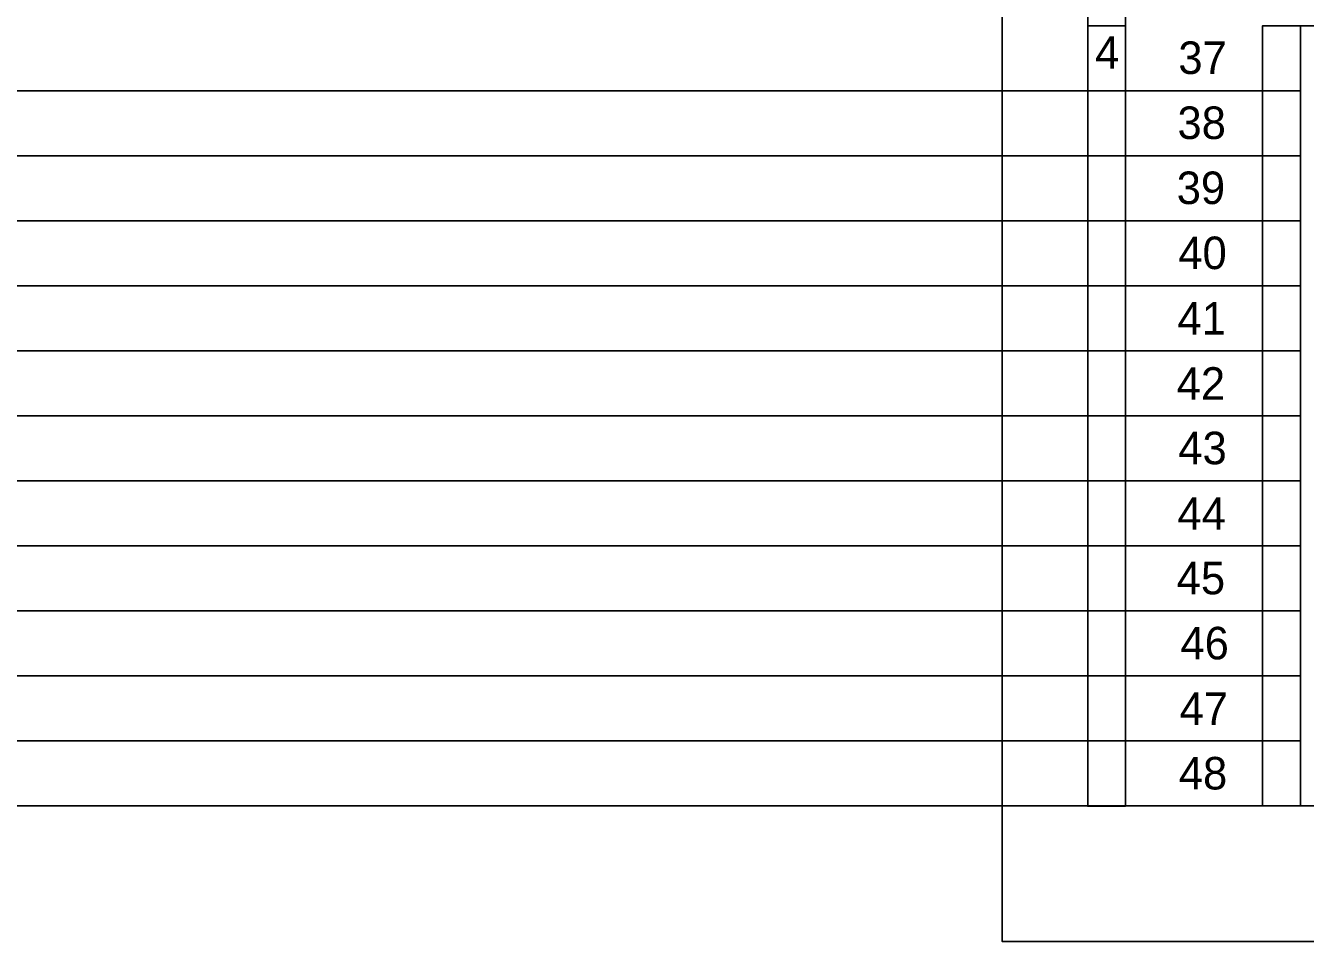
# Model space of a CAD drawing. Extents: x 1901 to 2519, y -3585 to -3154.
# Drawn here: x 2318.6 to 2387.9, y -3379.3 to -3329.7 of the extents above; entities that cross this region are included whole.
import ezdxf

# ---------------------------------------------------------------- set-up
doc = ezdxf.new("R2010")
doc.units = 0
doc.layers.add('rozvláknění', color=7, linetype='Continuous')

msp = doc.modelspace()

# ---------------------------------------------------------------- linework, layer by layer
at = {"layer": 'rozvláknění'}
for p, q in [((2253.932, -3333.246), (2385.56, -3333.245)), ((2253.932, -3336.764), (2385.56, -3336.763)), ((2253.932, -3340.282), (2385.56, -3340.281)), ((2253.932, -3343.8), (2385.56, -3343.799)), ((2253.932, -3347.318), (2385.56, -3347.318)), ((2253.932, -3350.837), (2385.56, -3350.836)), ((2253.932, -3354.355), (2385.56, -3354.354)), ((2253.932, -3357.873), (2385.56, -3357.872)), ((2253.932, -3361.391), (2385.56, -3361.39)), ((2253.932, -3364.909), (2385.56, -3364.909)), ((2253.932, -3368.428), (2385.56, -3368.427)), ((2253.932, -3371.946), (2385.56, -3371.945))]:
    msp.add_line(p, q, dxfattribs=at)
for points in [[(2371.457, -3178.543), (2405.455, -3178.542), (2405.455, -3379.276), (2371.457, -3379.276)], [(2378.138, -3371.959), (2376.097, -3371.959), (2376.097, -3287.487), (2378.138, -3287.487)], [(2378.138, -3371.945), (2376.097, -3371.945), (2376.097, -3329.727), (2378.138, -3329.727)], [(2385.56, -3329.727), (2387.602, -3329.727), (2387.602, -3333.245), (2385.56, -3333.245)], [(2385.56, -3329.727), (2387.602, -3329.727), (2387.602, -3333.245), (2385.56, -3333.245)], [(2387.602, -3329.727), (2390.389, -3329.727), (2390.389, -3371.941), (2387.602, -3371.941)], [(2385.56, -3333.245), (2387.602, -3333.245), (2387.602, -3336.763), (2385.56, -3336.763)], [(2385.56, -3333.245), (2387.602, -3333.245), (2387.602, -3336.763), (2385.56, -3336.763)], [(2385.56, -3336.763), (2387.602, -3336.763), (2387.602, -3340.281), (2385.56, -3340.281)], [(2385.56, -3336.763), (2387.602, -3336.763), (2387.602, -3340.281), (2385.56, -3340.281)], [(2385.56, -3340.281), (2387.602, -3340.281), (2387.602, -3343.799), (2385.56, -3343.799)], [(2385.56, -3340.281), (2387.602, -3340.281), (2387.602, -3343.799), (2385.56, -3343.799)], [(2385.56, -3343.799), (2387.602, -3343.799), (2387.602, -3347.318), (2385.56, -3347.318)], [(2385.56, -3343.799), (2387.602, -3343.799), (2387.602, -3347.318), (2385.56, -3347.318)], [(2385.56, -3347.318), (2387.602, -3347.318), (2387.602, -3350.836), (2385.56, -3350.836)], [(2385.56, -3347.318), (2387.602, -3347.318), (2387.602, -3350.836), (2385.56, -3350.836)], [(2385.56, -3350.836), (2387.602, -3350.836), (2387.602, -3354.354), (2385.56, -3354.354)], [(2385.56, -3350.836), (2387.602, -3350.836), (2387.602, -3354.354), (2385.56, -3354.354)], [(2385.56, -3354.354), (2387.602, -3354.354), (2387.602, -3357.872), (2385.56, -3357.872)], [(2385.56, -3354.354), (2387.602, -3354.354), (2387.602, -3357.872), (2385.56, -3357.872)], [(2385.56, -3357.872), (2387.602, -3357.872), (2387.602, -3361.39), (2385.56, -3361.39)], [(2385.56, -3357.872), (2387.602, -3357.872), (2387.602, -3361.39), (2385.56, -3361.39)], [(2385.56, -3361.39), (2387.602, -3361.39), (2387.602, -3364.909), (2385.56, -3364.909)], [(2385.56, -3361.39), (2387.602, -3361.39), (2387.602, -3364.909), (2385.56, -3364.909)], [(2385.56, -3364.909), (2387.602, -3364.909), (2387.602, -3368.427), (2385.56, -3368.427)], [(2385.56, -3364.909), (2387.602, -3364.909), (2387.602, -3368.427), (2385.56, -3368.427)], [(2385.56, -3368.427), (2387.602, -3368.427), (2387.602, -3371.945), (2385.56, -3371.945)], [(2385.56, -3368.427), (2387.602, -3368.427), (2387.602, -3371.945), (2385.56, -3371.945)]]:
    msp.add_lwpolyline(points, close=True, dxfattribs=at)
for points in [[(2378.138, -3329.727), (2376.097, -3329.727), (2376.097, -3371.945), (2378.138, -3371.945), (2378.138, -3329.727)], [(2378.138, -3329.727), (2376.097, -3329.727), (2376.097, -3371.945), (2378.138, -3371.945), (2378.138, -3329.727)], [(2378.138, -3329.727), (2376.097, -3329.727), (2376.097, -3371.945), (2378.138, -3371.945), (2378.138, -3329.727)], [(2378.138, -3329.727), (2376.097, -3329.727), (2376.097, -3371.945), (2378.138, -3371.945), (2378.138, -3329.727)], [(2378.138, -3329.727), (2376.097, -3329.727), (2376.097, -3371.945), (2378.138, -3371.945), (2378.138, -3329.727)], [(2378.138, -3329.727), (2376.097, -3329.727), (2376.097, -3371.945), (2378.138, -3371.945), (2378.138, -3329.727)], [(2385.56, -3333.245), (2387.602, -3333.245), (2387.602, -3329.727), (2385.56, -3329.727), (2385.56, -3333.245)], [(2385.56, -3333.245), (2387.602, -3333.245), (2387.602, -3329.727), (2385.56, -3329.727), (2385.56, -3333.245)], [(2385.56, -3333.245), (2387.602, -3333.245), (2387.602, -3329.727), (2385.56, -3329.727), (2385.56, -3333.245)], [(2385.56, -3333.245), (2387.602, -3333.245), (2387.602, -3329.727), (2385.56, -3329.727), (2385.56, -3333.245)], [(2385.56, -3333.245), (2387.602, -3333.245), (2387.602, -3329.727), (2385.56, -3329.727), (2385.56, -3333.245)], [(2385.56, -3333.245), (2387.602, -3333.245), (2387.602, -3329.727), (2385.56, -3329.727), (2385.56, -3333.245)], [(2385.56, -3333.245), (2387.602, -3333.245), (2387.602, -3329.727), (2385.56, -3329.727), (2385.56, -3333.245)], [(2385.56, -3333.245), (2387.602, -3333.245), (2387.602, -3329.727), (2385.56, -3329.727), (2385.56, -3333.245)], [(2385.56, -3333.245), (2387.602, -3333.245), (2387.602, -3329.727), (2385.56, -3329.727), (2385.56, -3333.245)], [(2385.56, -3333.245), (2387.602, -3333.245), (2387.602, -3329.727), (2385.56, -3329.727), (2385.56, -3333.245)], [(2385.56, -3333.243), (2385.56, -3368.443)], [(2385.56, -3336.763), (2387.602, -3336.763), (2387.602, -3333.245), (2385.56, -3333.245), (2385.56, -3336.763)], [(2385.56, -3336.763), (2387.602, -3336.763), (2387.602, -3333.245), (2385.56, -3333.245), (2385.56, -3336.763)], [(2385.56, -3336.763), (2387.602, -3336.763), (2387.602, -3333.245), (2385.56, -3333.245), (2385.56, -3336.763)], [(2385.56, -3336.763), (2387.602, -3336.763), (2387.602, -3333.245), (2385.56, -3333.245), (2385.56, -3336.763)], [(2385.56, -3336.763), (2387.602, -3336.763), (2387.602, -3333.245), (2385.56, -3333.245), (2385.56, -3336.763)], [(2385.56, -3336.763), (2387.602, -3336.763), (2387.602, -3333.245), (2385.56, -3333.245), (2385.56, -3336.763)], [(2385.56, -3336.763), (2387.602, -3336.763), (2387.602, -3333.245), (2385.56, -3333.245), (2385.56, -3336.763)], [(2385.56, -3336.763), (2387.602, -3336.763), (2387.602, -3333.245), (2385.56, -3333.245), (2385.56, -3336.763)], [(2385.56, -3336.763), (2387.602, -3336.763), (2387.602, -3333.245), (2385.56, -3333.245), (2385.56, -3336.763)], [(2385.56, -3336.763), (2387.602, -3336.763), (2387.602, -3333.245), (2385.56, -3333.245), (2385.56, -3336.763)], [(2385.56, -3340.281), (2387.602, -3340.281), (2387.602, -3336.763), (2385.56, -3336.763), (2385.56, -3340.281)], [(2385.56, -3340.281), (2387.602, -3340.281), (2387.602, -3336.763), (2385.56, -3336.763), (2385.56, -3340.281)], [(2385.56, -3340.281), (2387.602, -3340.281), (2387.602, -3336.763), (2385.56, -3336.763), (2385.56, -3340.281)], [(2385.56, -3340.281), (2387.602, -3340.281), (2387.602, -3336.763), (2385.56, -3336.763), (2385.56, -3340.281)], [(2385.56, -3340.281), (2387.602, -3340.281), (2387.602, -3336.763), (2385.56, -3336.763), (2385.56, -3340.281)], [(2385.56, -3340.281), (2387.602, -3340.281), (2387.602, -3336.763), (2385.56, -3336.763), (2385.56, -3340.281)], [(2385.56, -3340.281), (2387.602, -3340.281), (2387.602, -3336.763), (2385.56, -3336.763), (2385.56, -3340.281)], [(2385.56, -3340.281), (2387.602, -3340.281), (2387.602, -3336.763), (2385.56, -3336.763), (2385.56, -3340.281)], [(2385.56, -3340.281), (2387.602, -3340.281), (2387.602, -3336.763), (2385.56, -3336.763), (2385.56, -3340.281)], [(2385.56, -3340.281), (2387.602, -3340.281), (2387.602, -3336.763), (2385.56, -3336.763), (2385.56, -3340.281)], [(2385.56, -3343.799), (2387.602, -3343.799), (2387.602, -3340.281), (2385.56, -3340.281), (2385.56, -3343.799)], [(2385.56, -3343.799), (2387.602, -3343.799), (2387.602, -3340.281), (2385.56, -3340.281), (2385.56, -3343.799)], [(2385.56, -3343.799), (2387.602, -3343.799), (2387.602, -3340.281), (2385.56, -3340.281), (2385.56, -3343.799)], [(2385.56, -3343.799), (2387.602, -3343.799), (2387.602, -3340.281), (2385.56, -3340.281), (2385.56, -3343.799)], [(2385.56, -3343.799), (2387.602, -3343.799), (2387.602, -3340.281), (2385.56, -3340.281), (2385.56, -3343.799)], [(2385.56, -3343.799), (2387.602, -3343.799), (2387.602, -3340.281), (2385.56, -3340.281), (2385.56, -3343.799)], [(2385.56, -3343.799), (2387.602, -3343.799), (2387.602, -3340.281), (2385.56, -3340.281), (2385.56, -3343.799)], [(2385.56, -3343.799), (2387.602, -3343.799), (2387.602, -3340.281), (2385.56, -3340.281), (2385.56, -3343.799)], [(2385.56, -3343.799), (2387.602, -3343.799), (2387.602, -3340.281), (2385.56, -3340.281), (2385.56, -3343.799)], [(2385.56, -3343.799), (2387.602, -3343.799), (2387.602, -3340.281), (2385.56, -3340.281), (2385.56, -3343.799)], [(2385.56, -3347.318), (2387.602, -3347.318), (2387.602, -3343.799), (2385.56, -3343.799), (2385.56, -3347.318)], [(2385.56, -3347.318), (2387.602, -3347.318), (2387.602, -3343.799), (2385.56, -3343.799), (2385.56, -3347.318)], [(2385.56, -3347.318), (2387.602, -3347.318), (2387.602, -3343.799), (2385.56, -3343.799), (2385.56, -3347.318)], [(2385.56, -3347.318), (2387.602, -3347.318), (2387.602, -3343.799), (2385.56, -3343.799), (2385.56, -3347.318)], [(2385.56, -3347.318), (2387.602, -3347.318), (2387.602, -3343.799), (2385.56, -3343.799), (2385.56, -3347.318)], [(2385.56, -3347.318), (2387.602, -3347.318), (2387.602, -3343.799), (2385.56, -3343.799), (2385.56, -3347.318)], [(2385.56, -3347.318), (2387.602, -3347.318), (2387.602, -3343.799), (2385.56, -3343.799), (2385.56, -3347.318)], [(2385.56, -3347.318), (2387.602, -3347.318), (2387.602, -3343.799), (2385.56, -3343.799), (2385.56, -3347.318)], [(2385.56, -3347.318), (2387.602, -3347.318), (2387.602, -3343.799), (2385.56, -3343.799), (2385.56, -3347.318)], [(2385.56, -3347.318), (2387.602, -3347.318), (2387.602, -3343.799), (2385.56, -3343.799), (2385.56, -3347.318)], [(2385.56, -3350.836), (2387.602, -3350.836), (2387.602, -3347.318), (2385.56, -3347.318), (2385.56, -3350.836)], [(2385.56, -3350.836), (2387.602, -3350.836), (2387.602, -3347.318), (2385.56, -3347.318), (2385.56, -3350.836)], [(2385.56, -3350.836), (2387.602, -3350.836), (2387.602, -3347.318), (2385.56, -3347.318), (2385.56, -3350.836)], [(2385.56, -3350.836), (2387.602, -3350.836), (2387.602, -3347.318), (2385.56, -3347.318), (2385.56, -3350.836)], [(2385.56, -3350.836), (2387.602, -3350.836), (2387.602, -3347.318), (2385.56, -3347.318), (2385.56, -3350.836)], [(2385.56, -3350.836), (2387.602, -3350.836), (2387.602, -3347.318), (2385.56, -3347.318), (2385.56, -3350.836)], [(2385.56, -3350.836), (2387.602, -3350.836), (2387.602, -3347.318), (2385.56, -3347.318), (2385.56, -3350.836)], [(2385.56, -3350.836), (2387.602, -3350.836), (2387.602, -3347.318), (2385.56, -3347.318), (2385.56, -3350.836)], [(2385.56, -3350.836), (2387.602, -3350.836), (2387.602, -3347.318), (2385.56, -3347.318), (2385.56, -3350.836)], [(2385.56, -3350.836), (2387.602, -3350.836), (2387.602, -3347.318), (2385.56, -3347.318), (2385.56, -3350.836)], [(2385.56, -3354.354), (2387.602, -3354.354), (2387.602, -3350.836), (2385.56, -3350.836), (2385.56, -3354.354)], [(2385.56, -3354.354), (2387.602, -3354.354), (2387.602, -3350.836), (2385.56, -3350.836), (2385.56, -3354.354)], [(2385.56, -3354.354), (2387.602, -3354.354), (2387.602, -3350.836), (2385.56, -3350.836), (2385.56, -3354.354)], [(2385.56, -3354.354), (2387.602, -3354.354), (2387.602, -3350.836), (2385.56, -3350.836), (2385.56, -3354.354)], [(2385.56, -3354.354), (2387.602, -3354.354), (2387.602, -3350.836), (2385.56, -3350.836), (2385.56, -3354.354)], [(2385.56, -3354.354), (2387.602, -3354.354), (2387.602, -3350.836), (2385.56, -3350.836), (2385.56, -3354.354)], [(2385.56, -3354.354), (2387.602, -3354.354), (2387.602, -3350.836), (2385.56, -3350.836), (2385.56, -3354.354)], [(2385.56, -3354.354), (2387.602, -3354.354), (2387.602, -3350.836), (2385.56, -3350.836), (2385.56, -3354.354)], [(2385.56, -3354.354), (2387.602, -3354.354), (2387.602, -3350.836), (2385.56, -3350.836), (2385.56, -3354.354)], [(2385.56, -3354.354), (2387.602, -3354.354), (2387.602, -3350.836), (2385.56, -3350.836), (2385.56, -3354.354)], [(2385.56, -3357.872), (2387.602, -3357.872), (2387.602, -3354.354), (2385.56, -3354.354), (2385.56, -3357.872)], [(2385.56, -3357.872), (2387.602, -3357.872), (2387.602, -3354.354), (2385.56, -3354.354), (2385.56, -3357.872)], [(2385.56, -3357.872), (2387.602, -3357.872), (2387.602, -3354.354), (2385.56, -3354.354), (2385.56, -3357.872)], [(2385.56, -3357.872), (2387.602, -3357.872), (2387.602, -3354.354), (2385.56, -3354.354), (2385.56, -3357.872)], [(2385.56, -3357.872), (2387.602, -3357.872), (2387.602, -3354.354), (2385.56, -3354.354), (2385.56, -3357.872)], [(2385.56, -3357.872), (2387.602, -3357.872), (2387.602, -3354.354), (2385.56, -3354.354), (2385.56, -3357.872)], [(2385.56, -3357.872), (2387.602, -3357.872), (2387.602, -3354.354), (2385.56, -3354.354), (2385.56, -3357.872)], [(2385.56, -3357.872), (2387.602, -3357.872), (2387.602, -3354.354), (2385.56, -3354.354), (2385.56, -3357.872)], [(2385.56, -3357.872), (2387.602, -3357.872), (2387.602, -3354.354), (2385.56, -3354.354), (2385.56, -3357.872)], [(2385.56, -3357.872), (2387.602, -3357.872), (2387.602, -3354.354), (2385.56, -3354.354), (2385.56, -3357.872)], [(2385.56, -3361.39), (2387.602, -3361.39), (2387.602, -3357.872), (2385.56, -3357.872), (2385.56, -3361.39)], [(2385.56, -3361.39), (2387.602, -3361.39), (2387.602, -3357.872), (2385.56, -3357.872), (2385.56, -3361.39)], [(2385.56, -3361.39), (2387.602, -3361.39), (2387.602, -3357.872), (2385.56, -3357.872), (2385.56, -3361.39)], [(2385.56, -3361.39), (2387.602, -3361.39), (2387.602, -3357.872), (2385.56, -3357.872), (2385.56, -3361.39)], [(2385.56, -3361.39), (2387.602, -3361.39), (2387.602, -3357.872), (2385.56, -3357.872), (2385.56, -3361.39)], [(2385.56, -3361.39), (2387.602, -3361.39), (2387.602, -3357.872), (2385.56, -3357.872), (2385.56, -3361.39)], [(2385.56, -3361.39), (2387.602, -3361.39), (2387.602, -3357.872), (2385.56, -3357.872), (2385.56, -3361.39)], [(2385.56, -3361.39), (2387.602, -3361.39), (2387.602, -3357.872), (2385.56, -3357.872), (2385.56, -3361.39)], [(2385.56, -3361.39), (2387.602, -3361.39), (2387.602, -3357.872), (2385.56, -3357.872), (2385.56, -3361.39)], [(2385.56, -3361.39), (2387.602, -3361.39), (2387.602, -3357.872), (2385.56, -3357.872), (2385.56, -3361.39)], [(2385.56, -3364.909), (2387.602, -3364.909), (2387.602, -3361.39), (2385.56, -3361.39), (2385.56, -3364.909)], [(2385.56, -3364.909), (2387.602, -3364.909), (2387.602, -3361.39), (2385.56, -3361.39), (2385.56, -3364.909)], [(2385.56, -3364.909), (2387.602, -3364.909), (2387.602, -3361.39), (2385.56, -3361.39), (2385.56, -3364.909)], [(2385.56, -3364.909), (2387.602, -3364.909), (2387.602, -3361.39), (2385.56, -3361.39), (2385.56, -3364.909)], [(2385.56, -3364.909), (2387.602, -3364.909), (2387.602, -3361.39), (2385.56, -3361.39), (2385.56, -3364.909)], [(2385.56, -3364.909), (2387.602, -3364.909), (2387.602, -3361.39), (2385.56, -3361.39), (2385.56, -3364.909)], [(2385.56, -3364.909), (2387.602, -3364.909), (2387.602, -3361.39), (2385.56, -3361.39), (2385.56, -3364.909)], [(2385.56, -3364.909), (2387.602, -3364.909), (2387.602, -3361.39), (2385.56, -3361.39), (2385.56, -3364.909)], [(2385.56, -3364.909), (2387.602, -3364.909), (2387.602, -3361.39), (2385.56, -3361.39), (2385.56, -3364.909)], [(2385.56, -3364.909), (2387.602, -3364.909), (2387.602, -3361.39), (2385.56, -3361.39), (2385.56, -3364.909)], [(2385.56, -3368.427), (2387.602, -3368.427), (2387.602, -3364.909), (2385.56, -3364.909), (2385.56, -3368.427)], [(2385.56, -3368.427), (2387.602, -3368.427), (2387.602, -3364.909), (2385.56, -3364.909), (2385.56, -3368.427)], [(2385.56, -3368.427), (2387.602, -3368.427), (2387.602, -3364.909), (2385.56, -3364.909), (2385.56, -3368.427)], [(2385.56, -3368.427), (2387.602, -3368.427), (2387.602, -3364.909), (2385.56, -3364.909), (2385.56, -3368.427)], [(2385.56, -3368.427), (2387.602, -3368.427), (2387.602, -3364.909), (2385.56, -3364.909), (2385.56, -3368.427)], [(2385.56, -3368.427), (2387.602, -3368.427), (2387.602, -3364.909), (2385.56, -3364.909), (2385.56, -3368.427)], [(2385.56, -3368.427), (2387.602, -3368.427), (2387.602, -3364.909), (2385.56, -3364.909), (2385.56, -3368.427)], [(2385.56, -3368.427), (2387.602, -3368.427), (2387.602, -3364.909), (2385.56, -3364.909), (2385.56, -3368.427)], [(2385.56, -3368.427), (2387.602, -3368.427), (2387.602, -3364.909), (2385.56, -3364.909), (2385.56, -3368.427)], [(2385.56, -3368.427), (2387.602, -3368.427), (2387.602, -3364.909), (2385.56, -3364.909), (2385.56, -3368.427)], [(2385.56, -3371.945), (2387.602, -3371.945), (2387.602, -3368.427), (2385.56, -3368.427), (2385.56, -3371.945)], [(2385.56, -3371.945), (2387.602, -3371.945), (2387.602, -3368.427), (2385.56, -3368.427), (2385.56, -3371.945)], [(2385.56, -3371.945), (2387.602, -3371.945), (2387.602, -3368.427), (2385.56, -3368.427), (2385.56, -3371.945)], [(2385.56, -3371.945), (2387.602, -3371.945), (2387.602, -3368.427), (2385.56, -3368.427), (2385.56, -3371.945)], [(2385.56, -3371.945), (2387.602, -3371.945), (2387.602, -3368.427), (2385.56, -3368.427), (2385.56, -3371.945)], [(2385.56, -3371.945), (2387.602, -3371.945), (2387.602, -3368.427), (2385.56, -3368.427), (2385.56, -3371.945)], [(2385.56, -3371.945), (2387.602, -3371.945), (2387.602, -3368.427), (2385.56, -3368.427), (2385.56, -3371.945)], [(2385.56, -3371.945), (2387.602, -3371.945), (2387.602, -3368.427), (2385.56, -3368.427), (2385.56, -3371.945)], [(2385.56, -3371.945), (2387.602, -3371.945), (2387.602, -3368.427), (2385.56, -3368.427), (2385.56, -3371.945)], [(2385.56, -3371.945), (2387.602, -3371.945), (2387.602, -3368.427), (2385.56, -3368.427), (2385.56, -3371.945)]]:
    msp.add_lwpolyline(points, dxfattribs=at)

# ---------------------------------------------------------------- texts
for s, p in [('4', (2376.496, -3332.052)), ('4', (2376.496, -3332.052)), ('37', (2381, -3332.334)), ('38', (2380.953, -3335.854)), ('39', (2380.911, -3339.374)), ('40', (2381, -3342.894)), ('41', (2380.953, -3346.443)), ('42', (2380.911, -3349.963)), ('43', (2381, -3353.454)), ('44', (2380.953, -3357.003)), ('45', (2380.911, -3360.494)), ('46', (2381.113, -3364.014)), ('47', (2381.067, -3367.563)), ('48', (2381.025, -3371.054))]:
    msp.add_text(s, height=1.76, dxfattribs=at).set_placement(p)

doc.saveas('drawing.dxf')
